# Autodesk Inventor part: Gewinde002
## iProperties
Company: Menke GmbH
Created: 2009-11
Part Number: Gewinde002
Material: St.37-K
Description: =<Kurzbez.>-<BPbr>x<BPsr>x<BPlr>
Document SubType Name: Modeling
Designer: Hatay
Density: 7.85 g/cm^3
Ort: 52379 Langerwehe
Strasse: Am Parir 17
Tel und Fax: Tel:02423/3899-Fax:02423/901295
Rohmaß: =<Norm>-<BPbr>x<BPsr>x<BPlr>
Kurzbez.: Fl.
Norm: DIN 174
BPlr: 50
BPsr: 10
BPbr: 50
Author: Hatay
Comments: ---Alt---/ - Blankstahlerzeug.-DIN EN 10278/ - Warmge. Flachstahl-DIN EN 10058/ ---Neu---/ - Blanke Flachstahl-DIN 174/ - Warmge. Flachst.-DIN 1017-1/ - Warmge. Flachstäbe aus Stahl für allg. Verwendu
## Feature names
1. E01 [Extrusion]
2. Bohrung1 [Hole]
3. Bohrung2 [Hole]
